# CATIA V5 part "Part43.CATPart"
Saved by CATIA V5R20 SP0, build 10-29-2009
Part number: 9AE052430-4
Revision: ANY
Definition: UNKNOWN
Nomenclature: 9AE052430-4
Source: Unknown
Bounding box of the stored display mesh (mm): x -4.935 to 4.935, y -4.756 to 4.756, z -10 to 10
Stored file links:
  C:\Users\Utente\Desktop\IO LAVORO\3D X SITO CF\CUMSA\3D files AE\AE 082430\Part43.CATPart
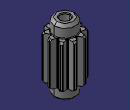
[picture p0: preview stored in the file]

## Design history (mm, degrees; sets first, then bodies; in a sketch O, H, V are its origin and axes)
Body1 "Cortar-Revolución1" (main body)
  Solid1: solid without history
